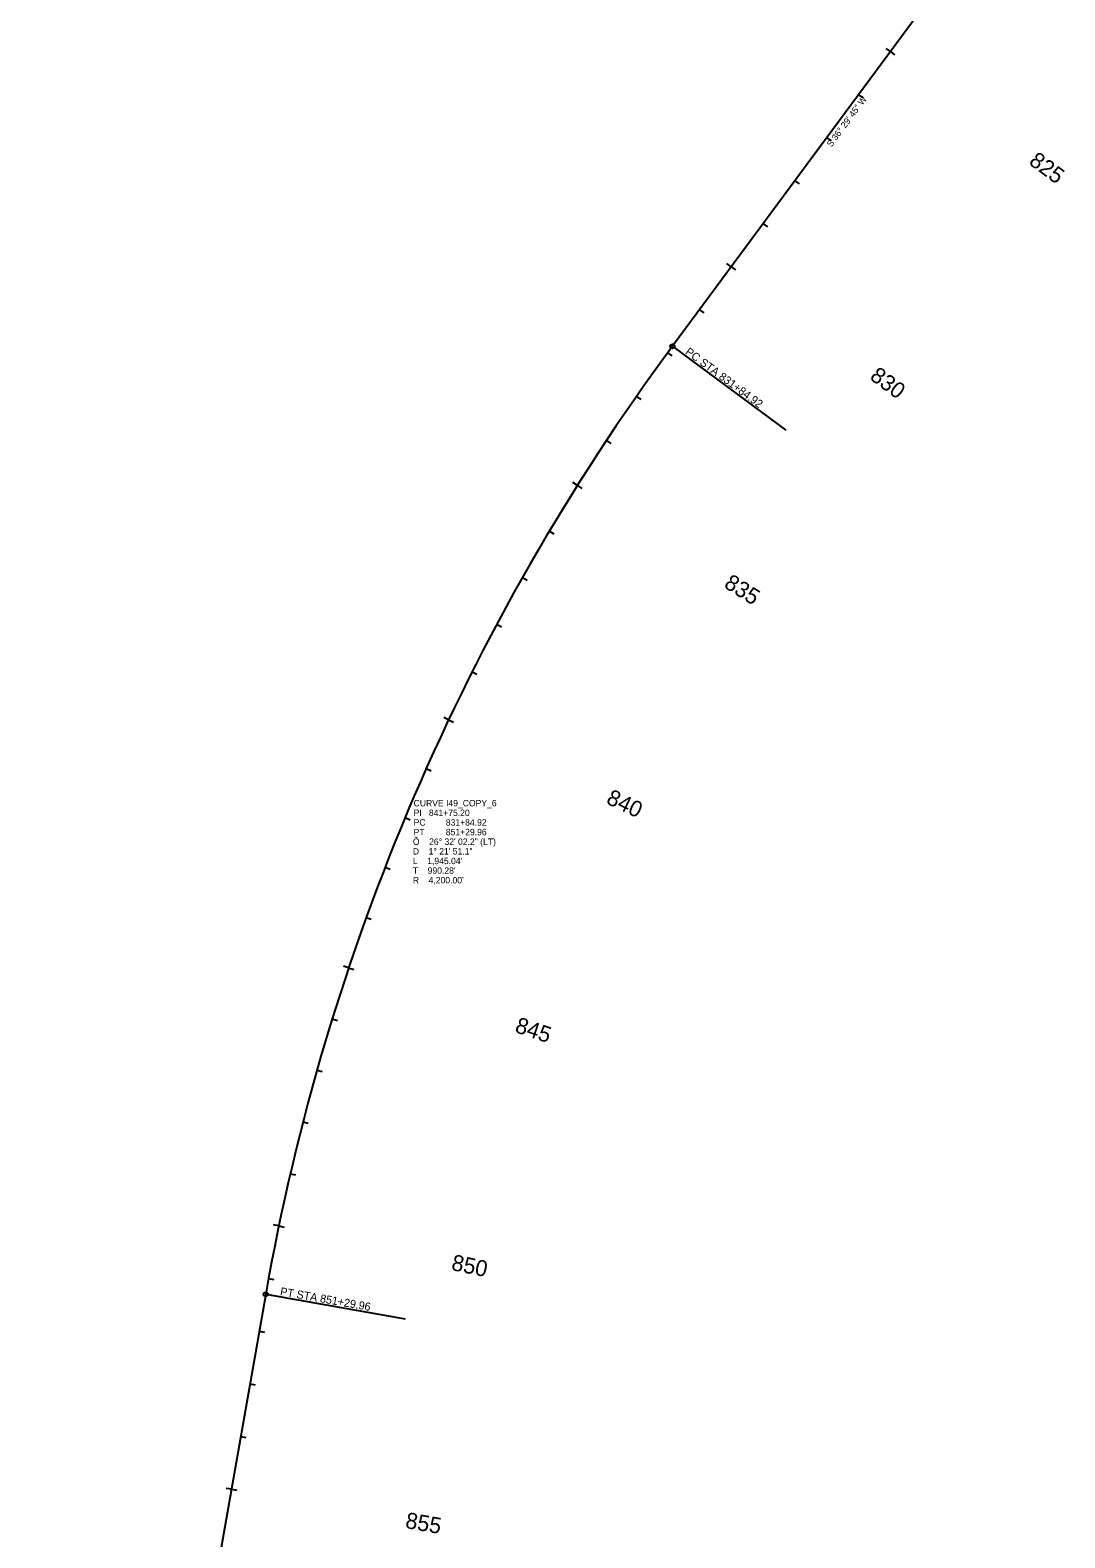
# Model space of a CAD drawing. Extents: x 2820825 to 2825694, y 116785 to 142398.
# Drawn here: x 2821007 to 2822941, y 133862 to 136679 of the extents above; entities that cross this region are included whole.
import ezdxf

# ---------------------------------------------------------------- set-up
doc = ezdxf.new("R2010")
doc.units = 0
for name, color, linetype in [('Default', 7, 'Continuous'), ('Roadway-Centerline main', 7, 'Continuous'), ('Roadway-Curve pc pt', 7, 'Continuous'), ('Text-Alignment info', 7, 'Continuous'), ('Text-Curve info', 7, 'Continuous')]:
    doc.layers.add(name, color=color, linetype=linetype)

msp = doc.modelspace()

# ---------------------------------------------------------------- linework, layer by layer
at = {"layer": 'Default'}
for p, q in [((2822878.3, 136994.9), (2822207.8, 136088.7)), ((2821447.5, 134317.2), (2821007.1, 131809.7))]:
    msp.add_line(p, q, dxfattribs=at)
msp.add_arc((2825584.2, 133590.7), 4200, 143.5041, 170.0381, dxfattribs=at)
at = {"layer": 'Roadway-Centerline main'}
for p, q in [((2822878.3, 136994.9), (2822207.8, 136088.7)), ((2822615.2, 136639.3), (2822607.1, 136645.2)), ((2822615.2, 136639.3), (2822623.2, 136633.3)), ((2822555.7, 136558.9), (2822563.7, 136553)), ((2822496.2, 136478.5), (2822504.3, 136472.6)), ((2822436.8, 136398.1), (2822444.8, 136392.2)), ((2822377.3, 136317.7), (2822385.3, 136311.8)), ((2822317.8, 136237.3), (2822309.8, 136243.3)), ((2822317.8, 136237.3), (2822325.8, 136231.4)), ((2822258.3, 136157), (2822266.4, 136151)), ((2822198.9, 136076.5), (2822206.9, 136070.6)), ((2822140.6, 135995.2), (2822148.8, 135989.5)), ((2822084.4, 135912.6), (2822092.7, 135907.1)), ((2822030.1, 135828.6), (2822021.6, 135833.9)), ((2822030.1, 135828.6), (2822038.5, 135823.3)), ((2821977.8, 135743.4), (2821986.4, 135738.2)), ((2821927.6, 135656.9), (2821936.3, 135652)), ((2821879.4, 135569.3), (2821888.3, 135564.5)), ((2821833.4, 135480.5), (2821842.3, 135476)), ((2821789.5, 135390.7), (2821780.4, 135394.9)), ((2821789.5, 135390.7), (2821798.5, 135386.4)), ((2821747.7, 135299.8), (2821756.8, 135295.7)), ((2821708.1, 135208), (2821717.3, 135204.1)), ((2821670.7, 135115.2), (2821680, 135111.6)), ((2821635.5, 135021.6), (2821644.9, 135018.2)), ((2821602.5, 134927.2), (2821593.1, 134930.4)), ((2821602.5, 134927.2), (2821612, 134924)), ((2821571.8, 134832.1), (2821581.4, 134829.1)), ((2821543.4, 134736.2), (2821553, 134733.5)), ((2821517.3, 134639.7), (2821527, 134637.2)), ((2821493.5, 134542.5), (2821503.2, 134540.3)), ((2821472, 134444.9), (2821462.2, 134446.9)), ((2821472, 134444.9), (2821481.8, 134442.8)), ((2821452.8, 134346.7), (2821462.6, 134344.9)), ((2821447.5, 134317.2), (2821007.1, 131809.7)), ((2821435.4, 134248.3), (2821445.2, 134246.5)), ((2821418.1, 134149.8), (2821427.9, 134148)), ((2821400.8, 134051.3), (2821410.6, 134049.6)), ((2821383.5, 133952.8), (2821373.7, 133954.5)), ((2821383.5, 133952.8), (2821393.3, 133951.1))]:
    msp.add_line(p, q, dxfattribs=at)
msp.add_arc((2825584.2, 133590.7), 4200, 143.5041, 170.0381, dxfattribs=at)
at = {"layer": 'Roadway-Curve pc pt'}
for p, q in [((2822211, 136086.3), (2822419.8, 135931.8)), ((2821451.5, 134316.6), (2821708, 134271.5))]:
    msp.add_line(p, q, dxfattribs=at)
for centre in [(2822207.8, 136088.7), (2821447.5, 134317.2)]:
    msp.add_circle(centre, 4, dxfattribs=at)

# ---------------------------------------------------------------- texts
at = {"layer": 'Roadway-Centerline main'}
for s, rotation, p in [(' 825', 323.5041, (2822863.5, 136436.9)), (' 830', 323.5041, (2822566.1, 136035)), (' 835', 327.8024, (2822292.9, 135645.4)), (' 840', 334.6233, (2822072.1, 135240)), (' 845', 341.4442, (2821901.1, 134811.2)), (' 850', 348.2651, (2821782.2, 134365.1)), (' 855', 350.0381, (2821696.1, 133882.7))]:
    msp.add_text(s, height=30, rotation=rotation, dxfattribs=at).set_placement(p)
at = {"layer": 'Roadway-Curve pc pt'}
for s, rotation, p in [('PC STA 831+84.92', 323.5041, (2822230.5, 136075.6)), ('PT STA 851+29.96', 350.0381, (2821473.6, 134315.7))]:
    msp.add_text(s, height=15, rotation=rotation, dxfattribs=at).set_placement(p)
at = {"layer": 'Text-Alignment info'}
msp.add_text('S 36%%d 29\' 45" W', height=12, rotation=53.5041, dxfattribs=at).set_placement((2822505, 136460.1))
at = {"layer": 'Text-Curve info'}
for s, p in [('CURVE I49_COPY_6', (2821724, 135229)), ('PI   841+75.20', (2821724, 135211)), ('PC', (2821724, 135193)), ('PT', (2821724, 135175)), ('831+84.92', (2821784.2, 135193)), ('851+29.96', (2821784.2, 135175)), ('Õ    26%%d 32\' 02.2" (LT)', (2821722.6, 135157)), ('D    1%%d 21\' 51.1"', (2821722.6, 135139)), ("L    1,945.04'", (2821722.6, 135121)), ("T    990.28'", (2821722.6, 135103)), ("R    4,200.00'", (2821722.6, 135085))]:
    msp.add_text(s, height=12, dxfattribs=at).set_placement(p)

doc.saveas('drawing.dxf')
